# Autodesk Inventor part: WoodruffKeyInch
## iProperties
Author: Administrator
Shininess: 62.0
PropertySet Name: _Private Model Information
Created: 2001-02
Part Number: WoodruffKeyInch
Document SubType Name: Modeling
Designer: C Bliss
Control State: 0
Master: False
Checked Out: False
PropertySet Name: Design Tracking Control
Density: 0.0
Volumn: 0.0
Area: 0.0
PropertySet Name: Model Information
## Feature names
1. KeyCenter [Extrusion]
2. RoundSides [Extrusion]
3. RoundBottom [Extrusion]
